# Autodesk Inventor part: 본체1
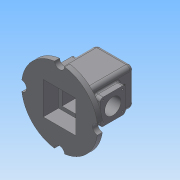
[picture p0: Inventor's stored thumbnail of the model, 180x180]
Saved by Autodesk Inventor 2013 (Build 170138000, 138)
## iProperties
Created: 2018-07
Part Number: 본체1
Material: 일반
Document SubType Name: Modeling
Designer: Administrator
Density: 1 g/cm^3
Author: Administrator
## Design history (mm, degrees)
node "작업 평면1"
sketch "스케치13"
  geometry: C1 r 75 at (0, 0); 1 further point
  constraints: 1 centre point, 1 coincident
  dimensions: "d63" = 150 diameter of C1
extrude "돌출10" join sketch "스케치13" distance "d64" = 10; taper "d65" = 0 deg
sketch "스케치14"
  geometry: C1 r 75 at (0, 0) reference; C2 r 10 at (75, 0); 2 further points
  constraints: 2 horizontal alignment, 1 centre point, 2 other
  dimensions: "d67" = 20 diameter of C2; "d68" = 75 distance of C1.centre C2.centre
extrude "돌출11" cut sketch "스케치14" distance "d69" = 10; taper "d70" = 0 deg
sketch "스케치17"
  geometry: L1 (-32, 32)-(32, 32); L2 (32, 32)-(32, -32); L3 (32, -32)-(-32, -32); L4 (-32, -32)-(-32, 32); A1 r 5 centre (0, 75) between (-4.997, 74.833) and (4.997, 74.833) reference; A2 r 75 centre (0, 0) between (74.333, 9.978) and (74.333, -9.978) reference; A3 r 5 centre (-75, 0) between (-74.833, -4.997) and (-74.833, 4.997) reference; A4 r 75 centre (0, 0) between (74.333, 9.978) and (74.333, -9.978) reference; A5 r 5 centre (0, -75) between (4.997, -74.833) and (-4.997, -74.833) reference; A6 r 75 centre (0, 0) between (74.333, 9.978) and (74.333, -9.978) reference; A7 r 10 centre (75, 0) between (74.333, 9.978) and (74.333, -9.978) reference; A8 r 75 centre (0, 0) between (74.333, 9.978) and (74.333, -9.978) reference; 2 further points
  constraints: 8 end point, 2 midpoint, 2 parallel, 1 horizontal, 1 horizontal alignment, 1 perpendicular, 1 vertical alignment
  dimensions: "d84" = 64 distance of L2.end L3.end; "d85" = 64 distance of L1.end L2.end
node "작업 평면4"
sketch "스케치19"
  geometry: A1 r 10 centre (75, 0) between (74.333, 9.978) and (74.333, -9.978) reference; A2 r 75 centre (0, 0) between (74.333, 9.978) and (74.333, -9.978) reference
sketch "스케치20"
  geometry: L1 (-37, 37)-(37, 37); L2 (37, 37)-(37, -37); L3 (37, -37)-(-37, -37); L4 (-37, -37)-(-37, 37); A1 r 75 centre (0, 0) between (74.333, 9.978) and (74.333, -9.978) reference; 2 further points
  constraints: 8 end point, 2 midpoint, 2 parallel, 1 horizontal, 1 horizontal alignment, 1 perpendicular, 1 vertical alignment
  dimensions: "d90" = 74 distance of L1.start L1.end; "d92" = 74 distance of L1.end L2.end
extrude "돌출15" join sketch "스케치20" distance "d93" = 100; taper "d94" = 0 deg
sketch "스케치21"
  geometry: L1 (-20, 20)-(20, 20); L2 (20, 20)-(20, -20); L3 (20, -20)-(-20, -20); L4 (-20, -20)-(-20, 20); 3 further points
  constraints: 8 end point, 2 midpoint, 2 parallel, 1 horizontal, 1 horizontal alignment, 1 perpendicular, 1 vertical alignment
  dimensions: "d95" = 40 distance of L2.end L3.end; "d96" = 40 distance of L1.end L2.end
extrude "돌출16" join sketch "스케치21" distance "d97" = 7; taper "d98" = 0 deg
sketch "스케치22"
  geometry: C1 r 17.5 at (0, 0); 1 further point
  constraints: 1 centre point, 1 coincident
  dimensions: "d99" = 35 diameter of C1
extrude "돌출17" join sketch "스케치22" distance "d100" = 3; taper "d101" = 0 deg
sketch "스케치23"
  geometry: C1 r 17.5 at (0, 0) reference; C2 r 14 at (0, 0)
  constraints: 1 centre point, 1 coincident
  dimensions: "d103" = 28 diameter of C2
extrude "돌출18" cut sketch "스케치23" distance "d104" = 4; taper "d105" = 0 deg
sketch "스케치24"
  geometry: C1 r 14 at (0, 0) reference; C2 r 10.5 at (0, 0)
  constraints: 1 centre point, 1 coincident
  dimensions: "d106" = 21 diameter of C2
extrude "돌출19" cut sketch "스케치24" stored distance "d107" = 4; taper "d108" = 0 deg
sketch "스케치25"
  geometry: L1 (74, 0)-(0, 0) reference; L2 (74, 0)-(74, 100) reference; L3 (0, 100)-(74, 100) reference; L4 (0, 0)-(0, 100) reference; 1 further point
sketch "스케치26"
  geometry: L1 (74, 0)-(0, 0) reference; L2 (74, 0)-(74, 100) reference; L3 (0, 100)-(74, 100) reference; L4 (0, 0)-(0, 100) reference; L5 (-28.238, 0)-(0, 0) reference; L6 (0, 0)-(74, 0) reference; L7 (74, 0)-(102.238, 0) reference; L8 (102.238, 0)-(102.238, -10) reference; L9 (102.238, -10)-(-28.238, -10) reference; L10 (-28.238, -10)-(-28.238, 0) reference; L11 (0, 0)-(0, 100) reference; L12 (0, 100)-(74, 100) reference; L13 (74, 100)-(74, 0) reference; 1 further point
  node "절단 모서리 투영5"
node "작업 평면6"
sketch "스케치27"
  geometry: L1 (-58, 74.333)-(-58, 9.978) reference; C1 r 16 at (-3, 0); 1 further point
  constraints: 1 centre point
  dimensions: "d113" = 32 diameter of C1; "d114" = 55 distance from line of L1 C1.centre
sketch "스케치28"
  geometry: L1 (22, 25)-(-28, 25); L2 (-28, 25)-(-28, -25); L3 (-28, -25)-(22, -25); L4 (22, -25)-(22, 25); L5 (-48, 55.902)-(-48, -55.902) reference; L6 (-48, -55.902)-(-58, -55.902) reference; L7 (-58, -55.902)-(-58, 55.902) reference; L8 (-58, 55.902)-(-48, 55.902) reference; 2 further points
  constraints: 8 end point, 2 parallel, 1 horizontal, 1 horizontal alignment, 1 midpoint, 1 perpendicular
  dimensions: "d115" = 50 distance of L3.end L1.start; "d117" = 50 distance of L2.end L3.end; "d120" = 80 distance between parallel lines of L7 L4
extrude "돌출21" join sketch "스케치28" stored distance "d121" = 4; taper "d122" = 0 deg
extrude "돌출22" cut sketch "스케치27" stored distance "d123" = 4; taper "d124" = 0 deg
sketch "스케치29"
  geometry: L1 (-25, 22)-(-25, -28) reference; L2 (-25, -28)-(25, -28) reference; L3 (25, -28)-(25, 22) reference; L4 (25, 22)-(-25, 22) reference; C1 r 16 at (0, -3) reference; 1 further point
fillet "모깎기1" dims "d125" = 8
fillet "모깎기2" dims "d126" = 8
fillet "모깎기3" dims "d127" = 3
fillet "모깎기4" dims "d128" = 3
fillet "모깎기5" dims "d129" = 3
fillet "모깎기6" dims "d130" = 6
fillet "모깎기7" dims "d131" = 3
sketch "스케치30"
  geometry: L1 (-32, 32)-(32, 32); L2 (32, 32)-(32, -32); L3 (32, -32)-(-32, -32); L4 (-32, -32)-(-32, 32); C1 r 10.5 at (0, 0) reference; A1 r 75 centre (0, 0) between (9.978, -74.333) and (74.333, -9.978) reference; 2 further points
  constraints: 8 end point, 2 midpoint, 2 parallel, 1 horizontal, 1 horizontal alignment, 1 perpendicular, 1 vertical alignment
  dimensions: "d132" = 64 distance of L1.start L1.end; "d135" = 64 distance of L1.end L2.end
extrude "돌출23" cut sketch "스케치30" distance "d136" = 30; taper "d137" = 0 deg
sketch "스케치31"
  geometry: L1 (-25, 25)-(25, 25); L2 (25, 25)-(25, -25); L3 (25, -25)-(-25, -25); L4 (-25, -25)-(-25, 25); C1 r 10.5 at (0, 0) reference; 2 further points
  constraints: 8 end point, 2 midpoint, 2 parallel, 1 horizontal, 1 horizontal alignment, 1 perpendicular, 1 vertical alignment
  dimensions: "d138" = 50 distance of L1.start L1.end; "d140" = 50 distance of L1.end L2.end
extrude "돌출24" cut sketch "스케치31" distance "d141" = 50; taper "d142" = 0 deg
sketch "스케치32"
  geometry: L1 (-32, 32)-(32, 32); L2 (32, 32)-(32, -32); L3 (32, -32)-(-32, -32); L4 (-32, -32)-(-32, 32); C1 r 10.5 at (0, 0) reference; 2 further points
  constraints: 8 end point, 2 midpoint, 2 parallel, 1 horizontal, 1 horizontal alignment, 1 perpendicular, 1 vertical alignment
  dimensions: "d143" = 64 distance of L1.end L2.end; "d145" = 64 distance of L1.start L1.end
extrude "돌출25" cut sketch "스케치32" distance "d146" = 25; taper "d147" = 0 deg
sketch "스케치33"
  geometry: L1 (66, -89)-(66, 0) reference; L2 (46.5, 18)-(11.5, 18) reference; 2 further points
  constraints: 1 other
  dimensions: "d148" = 37 distance from line of L1 point (29, -12); "d149" = 30 distance from line of point (29, -12) L2
feature "엠보싱1" sketch "스케치33" dims "d150" = 0.5, "d151" = 0
sketch "스케치38"
  geometry: A1 r 6 centre (-19, 16) between (-19, 22) and (-25, 16) reference; 2 further points
  constraints: 1 coincident
hole "구멍3" sketch "스케치38" at (-19, 16) diameter "d164" = 3.242; stored, may be unused: countersink angle "d168" = 90 deg, drill point angle "d170" = 118 deg; dims "d165" = 8, "d166" = 4, "d167" = 2, "d169" = 10
fillet "모깎기8" dims "d174" = 3
sketch "스케치39"
  geometry: L1 (37, -31)-(37, -45) reference; L2 (40, -48)-(65, -48) reference; L3 (65, -48)-(65, -58) reference; L4 (65, -58)-(32, -58) reference; L5 (32, -58)-(32, -28) reference; L6 (32, -28)-(25, -28) reference; L7 (25, -28)-(25, -19) reference; L8 (25, -19)-(50, -19) reference; L9 (50, -19)-(50, -28) reference; L10 (50, -28)-(40, -28) reference; L11 (-40, -28)-(-50, -28) reference; L12 (-50, -28)-(-50, -19) reference; L13 (-50, -19)-(-25, -19) reference; L14 (-25, -19)-(-25, -28) reference; L15 (-25, -28)-(-32, -28) reference; L16 (-32, -28)-(-32, -58) reference; L17 (-32, -58)-(-65, -58) reference; L18 (-65, -58)-(-65, -48) reference; L19 (-65, -48)-(-40, -48) reference; L20 (-37, -45)-(-37, -31) reference; L21 (-17.5, 59)-(-17.5, 62) reference; L22 (-17.5, 62)-(-14, 62) reference; L23 (-14, 62)-(-14, 58) reference; L24 (-14, 58)-(-10.5, 58) reference; L25 (-10.5, 58)-(-10.5, 47) reference; L26 (-10.5, 47)-(-29, 47) reference; L27 (-32, 44)-(-32, 22) reference; L28 (-32, 22)-(-25, 22) reference; L29 (-25, 22)-(-25, 13) reference; L30 (-25, 13)-(-50, 13) reference; L31 (-50, 13)-(-50, 22) reference; L32 (-50, 22)-(-40, 22) reference; L33 (-37, 25)-(-37, 44) reference; L34 (-29, 52)-(-23, 52) reference; L35 (-20, 55)-(-20, 59) reference; L36 (-20, 59)-(-17.5, 59) reference; L37 (17.5, 62)-(17.5, 59) reference; L38 (17.5, 59)-(20, 59) reference; L39 (20, 59)-(20, 55) reference; L40 (23, 52)-(29, 52) reference; L41 (37, 44)-(37, 33.671) reference; L42 (37, 33.671)-(37.5, 33.671) reference; L43 (37.5, 33.671)-(37.5, 33.416) reference; L44 (37.5, 33.416)-(37, 33.416) reference; L45 (37, 33.416)-(37, 25) reference; L46 (40, 22)-(50, 22) reference; L47 (50, 22)-(50, 13) reference; L48 (50, 13)-(25, 13) reference; L49 (25, 13)-(25, 22) reference; L50 (25, 22)-(32, 22) reference; L51 (32, 22)-(32, 44) reference; L52 (29, 47)-(10.5, 47) reference; L53 (10.5, 47)-(10.5, 58) reference; L54 (10.5, 58)-(14, 58) reference; L55 (14, 58)-(14, 62) reference; L56 (14, 62)-(17.5, 62) reference; L57 (37, -31)-(37, -45) reference; L58 (40, -48)-(65, -48) reference; L59 (65, -48)-(65, -58) reference; L60 (65, -58)-(32, -58) reference; L61 (32, -58)-(32, -28) reference; L62 (32, -28)-(25, -28) reference; L63 (25, -28)-(25, -19) reference; L64 (25, -19)-(50, -19) reference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; A1 r 3 centre (40, -31) between (40, -28) and (37, -31) reference; A2 r 3 centre (40, -45) between (37, -45) and (40, -48) reference; A3 r 3 centre (-40, -31) between (-37, -31) and (-40, -28) reference; A4 r 3 centre (-40, -45) between (-40, -48) and (-37, -45) reference; A5 r 3 centre (-29, 44) between (-29, 47) and (-32, 44) reference; A6 r 3 centre (-40, 25) between (-40, 22) and (-37, 25) reference; A7 r 8 centre (-29, 44) between (-29, 52) and (-37, 44) reference; A8 r 3 centre (-23, 55) between (-23, 52) and (-20, 55) reference; A9 r 3 centre (23, 55) between (20, 55) and (23, 52) reference; A10 r 8 centre (29, 44) between (37, 44) and (29, 52) reference; A11 r 3 centre (40, 25) between (37, 25) and (40, 22) reference; A12 r 3 centre (29, 44) between (32, 44) and (29, 47) reference; A13 r 3 centre (40, -31) between (40, -28) and (37, -31) reference; A14 r 3 centre (40, -45) between (37, -45) and (40, -48) reference; A15 r 3 centre (-40, -31) between (-37, -31) and (-40, -28) reference; A16 r 3 centre (-40, -45) between (-40, -48) and (-37, -45) reference; A17 r 3 centre (-29, 44) between (-29, 47) and (-32, 44) reference; A18 r 3 centre (-40, 25) between (-40, 22) and (-37, 25) reference; A19 r 8 centre (-29, 44) between (-29, 52) and (-37, 44) reference; A20 r 3 centre (-23, 55) between (-23, 52) and (-20, 55) reference; A21 r 3 centre (23, 55) between (20, 55) and (23, 52) reference; A22 r 8 centre (29, 44) between (37, 44) and (29, 52) reference; A23 r 3 centre (40, 25) between (37, 25) and (40, 22) reference; A24 r 3 centre (29, 44) between (32, 44) and (29, 47) reference; 1 further point
  constraints: 6 end point, 2 collinear, 1 point on line
  dimensions: "d175" = 110 deg angle of L113 L27
extrude "돌출26" cut sketch "스케치39" stored distance "d176" = 60; taper "d177" = 0 deg
sketch "스케치41"
  geometry: L1 (59, 17.5)-(62, 17.5) reference; L2 (62, 17.5)-(62, 14) reference; L3 (62, 14)-(58, 14) reference; L4 (58, 14)-(58, 10.5) reference; L5 (58, 10.5)-(47, 10.5) reference; L6 (47, 10.5)-(47, 29) reference; L7 (44, 32)-(22, 32) reference; L8 (22, 32)-(22, 25) reference; L9 (22, 25)-(-28, 25) reference; L10 (-28, 25)-(-28, 32) reference; L11 (-28, 32)-(-58, 32) reference; L12 (-58, 32)-(-58, 65) reference; L13 (-58, 65)-(-48, 65) reference; L14 (-48, 65)-(-48, 40) reference; L15 (-45, 37)-(44, 37) reference; L16 (52, 29)-(52, 23) reference; L17 (55, 20)-(59, 20) reference; L18 (59, 20)-(59, 17.5) reference; L19 (62, -17.5)-(59, -17.5) reference; L20 (59, -17.5)-(59, -20) reference; L21 (59, -20)-(55, -20) reference; L22 (52, -23)-(52, -29) reference; L23 (44, -37)-(-45, -37) reference; L24 (-48, -40)-(-48, -65) reference; L25 (-48, -65)-(-58, -65) reference; L26 (-58, -65)-(-58, -32) reference; L27 (-58, -32)-(-28, -32) reference; L28 (-28, -32)-(-28, -25) reference; L29 (-28, -25)-(22, -25) reference; L30 (22, -25)-(22, -32) reference; L31 (22, -32)-(44, -32) reference; L32 (47, -29)-(47, -10.5) reference; L33 (47, -10.5)-(58, -10.5) reference; L34 (58, -10.5)-(58, -14) reference; L35 (58, -14)-(62, -14) reference; L36 (62, -14)-(62, -17.5) reference; L37 (22, 32)-(19.452, 25); L38 (19.452, 25)-(22, 25); L39 (22, 25)-(22, 32); A1 r 3 centre (44, 29) between (47, 29) and (44, 32) reference; A2 r 3 centre (-45, 40) between (-48, 40) and (-45, 37) reference; A3 r 8 centre (44, 29) between (52, 29) and (44, 37) reference; A4 r 3 centre (55, 23) between (52, 23) and (55, 20) reference; A5 r 3 centre (55, -23) between (55, -20) and (52, -23) reference; A6 r 8 centre (44, -29) between (44, -37) and (52, -29) reference; A7 r 3 centre (-45, -40) between (-45, -37) and (-48, -40) reference; A8 r 3 centre (44, -29) between (44, -32) and (47, -29) reference; 1 further point
  constraints: 6 end point, 1 collinear, 1 perpendicular, 1 point on line
  dimensions: "d178" = 110 deg angle of L37 L7
extrude "돌출27" cut sketch "스케치41" stored distance "d179" = 60; taper "d180" = 0 deg
sketch "스케치42"
  geometry: 1 further point
node "솔리드2"
pattern_circular "원형 패턴4" dims angle "d110" = 360 deg
mirror "대칭2"
pattern_circular "원형 패턴5" dims angle "d172" = 360 deg
mirror "대칭3"
mirror "대칭4"
mirror "대칭5"
node "절단 모서리 투영2"
node "절단 모서리 투영3"
node "절단 모서리 투영6"
node "절단 모서리 투영10"
node "절단 모서리 투영11"
node "절단 모서리 투영12"
